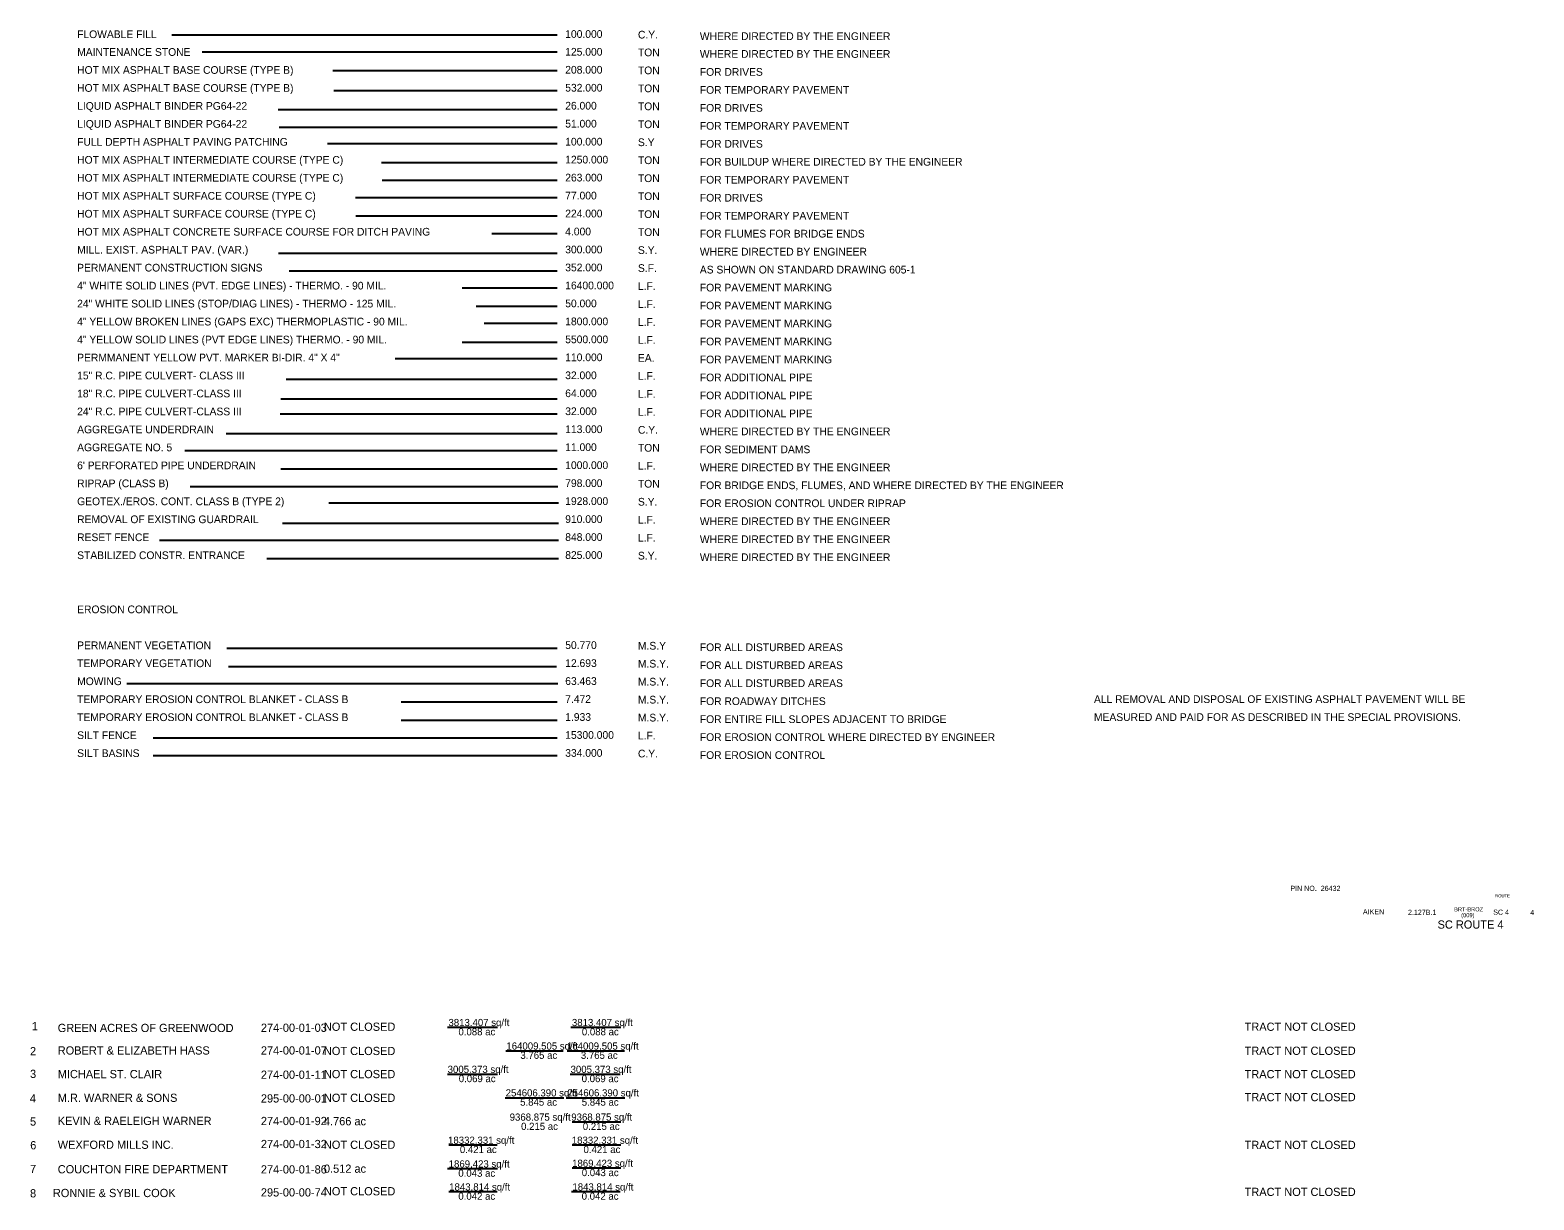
# Model space of a CAD drawing. Extents: x 17139 to 21295, y 12843 to 18076.
# Drawn here: x 17386 to 18851, y 13166 to 14305 of the extents above; entities that cross this region are included whole.
import ezdxf

# ---------------------------------------------------------------- set-up
doc = ezdxf.new("R2010")
doc.units = 0
for name, color, linetype in [('Level 1', 7, 'Continuous'), ('Level 23', 7, 'Continuous'), ('Level 3', 7, 'Continuous')]:
    doc.layers.add(name, color=color, linetype=linetype)

msp = doc.modelspace()

# ---------------------------------------------------------------- linework, layer by layer
at = {"layer": 'Level 1'}
for p, q in [((17792.8, 13334.5), (17841.4, 13334.5)), ((17912.9, 13334.5), (17961.5, 13334.5)), ((17849.5, 13311.7), (17905.3, 13311.7)), ((17909.2, 13311.7), (17965, 13311.7)), ((17792.8, 13288.9), (17841.4, 13288.9)), ((17912.2, 13288.9), (17960.8, 13288.9)), ((17848.8, 13266), (17906, 13266)), ((17908.1, 13266), (17965.3, 13266)), ((17914.2, 13242.6), (17961.3, 13242.6)), ((17793.8, 13220.2), (17840.9, 13220.2)), ((17914.2, 13220.2), (17961.3, 13220.2)), ((17792.8, 13197.1), (17841.4, 13197.1)), ((17914.2, 13197.7), (17961.3, 13197.7)), ((17793.8, 13174.5), (17841.1, 13174.5)), ((17913.5, 13174.5), (17960.7, 13174.5))]:
    msp.add_line(p, q, dxfattribs=at)
at = {"layer": 'Level 23'}
for p, q in [((17524.3, 14300.7), (17899.3, 14300.7)), ((17553.9, 14284.3), (17899.3, 14284.3)), ((17681, 14266.2), (17899.3, 14266.2)), ((17681.9, 14246.7), (17899.3, 14246.7)), ((17627.9, 14228.2), (17899.3, 14228.2)), ((17628.6, 14211), (17899.3, 14211)), ((17675.8, 14194.9), (17899.3, 14194.9)), ((17728.4, 14176.4), (17899.3, 14176.4)), ((17728.9, 14159.2), (17899.3, 14159.2)), ((17702.9, 14142.6), (17899.3, 14142.6)), ((17703.3, 14124.7), (17899.3, 14124.7)), ((17835.8, 14107.5), (17899.3, 14107.5)), ((17628, 14088.3), (17899.3, 14088.3)), ((17638.3, 14071.1), (17899.3, 14071.1)), ((17806.8, 14054.5), (17899.3, 14054.5)), ((17820.7, 14036.6), (17899.3, 14036.6)), ((17828.4, 14020.1), (17899.3, 14020.1)), ((17806.8, 14001.5), (17899.3, 14001.5)), ((17741.7, 13985.7), (17899.3, 13985.7)), ((17635.4, 13965.7), (17899.3, 13965.7)), ((17630.3, 13946.5), (17899.3, 13946.5)), ((17629.7, 13932), (17899.3, 13932)), ((17577.2, 13912.7), (17899.3, 13912.7)), ((17536.7, 13896.2), (17899.3, 13896.2)), ((17630.4, 13878.3), (17899.3, 13878.3)), ((17542, 13861.1), (17900, 13861.1)), ((17677.1, 13845.3), (17900.8, 13845.3)), ((17632.1, 13825.3), (17900.8, 13825.3)), ((17512.1, 13808.8), (17900.8, 13808.8)), ((17616.8, 13790.9), (17900.8, 13790.9)), ((17577.7, 13703.7), (17899.3, 13703.7)), ((17579.4, 13685.8), (17898.9, 13685.8)), ((17480.3, 13669.3), (17900, 13669.3)), ((17747.5, 13651.4), (17899.3, 13651.4)), ((17747.5, 13633.5), (17899.3, 13633.5)), ((17506.1, 13616.3), (17899.3, 13616.3)), ((17506.1, 13599.1), (17899.3, 13599.1))]:
    msp.add_line(p, q, dxfattribs=at)

# ---------------------------------------------------------------- texts
at = {"layer": 'Level 1'}
for s, height, p in [('3813.407 sq/ft', 7, (17793.6, 13335.7)), ('3813.407 sq/ft', 7, (17913.8, 13335.7)), ('1', 8, (17387.8, 13331.6)), ('GREEN ACRES OF GREENWOOD', 8, (17413.1, 13329.9)), ('274-00-01-03', 8, (17610.9, 13330.1)), ('NOT CLOSED', 8, (17672.3, 13331.1)), ('0.088 ac', 7, (17803.3, 13326.7)), ('0.088 ac', 7, (17923.5, 13326.7)), ('TRACT NOT CLOSED', 8, (18568.9, 13331.1)), ('2', 8, (17386.1, 13307.3)), ('ROBERT & ELIZABETH HASS', 8, (17413.1, 13308)), ('274-00-01-07', 8, (17610.9, 13308)), ('NOT CLOSED', 8, (17672.3, 13307.5)), ('164009.505 sq/ft', 7, (17850, 13312.8)), ('164009.505 sq/ft', 7, (17909, 13312.8)), ('TRACT NOT CLOSED', 8, (18568.9, 13307.7)), ('3005.373 sq/ft', 7, (17792.8, 13290.1)), ('3.765 ac', 7, (17863.6, 13303.8)), ('3005.373 sq/ft', 7, (17912.5, 13290.1)), ('3.765 ac', 7, (17922.5, 13303.8)), ('3', 8, (17386.1, 13285.2)), ('MICHAEL ST. CLAIR', 8, (17413.1, 13285)), ('274-00-01-11', 8, (17610.9, 13284.4)), ('NOT CLOSED', 8, (17672.3, 13285)), ('0.069 ac', 7, (17803.6, 13281.1)), ('0.069 ac', 7, (17923.3, 13281.1)), ('TRACT NOT CLOSED', 8, (18568.9, 13284.9)), ('4', 8, (17385.9, 13261.4)), ('M.R. WARNER & SONS', 8, (17413.1, 13261.9)), ('295-00-00-01', 8, (17610.9, 13261.3)), ('NOT CLOSED', 8, (17672.3, 13261.9)), ('254606.390 sq/ft', 7, (17849.3, 13267.2)), ('254606.390 sq/ft', 7, (17909.3, 13267.2)), ('TRACT NOT CLOSED', 8, (18568.9, 13262.6)), ('5.845 ac', 7, (17863.4, 13258.2)), ('5.845 ac', 7, (17923.4, 13258.2)), ('5', 8, (17386.1, 13238.8)), ('KEVIN & RAELEIGH WARNER', 8, (17413.1, 13239.4)), ('274-00-01-92', 8, (17610.9, 13239.3)), ('4.766 ac', 8, (17672.3, 13239.1)), ('9368.875 sq/ft', 7, (17853.2, 13243.6)), ('0.215 ac', 7, (17864.3, 13234.6)), ('9368.875 sq/ft', 7, (17913.2, 13243.6)), ('0.215 ac', 7, (17924.4, 13234.6)), ('WEXFORD MILLS INC.', 8, (17413.1, 13216.2)), ('274-00-01-32', 8, (17610.9, 13216.9)), ('NOT CLOSED', 8, (17672.3, 13216.2)), ('18332.331 sq/ft', 7, (17793.2, 13221.1)), ('18332.331 sq/ft', 7, (17913.7, 13221.1)), ('6', 8, (17386.3, 13215.7)), ('0.421 ac', 7, (17804.7, 13212.1)), ('0.421 ac', 7, (17925.1, 13212.1)), ('TRACT NOT CLOSED', 8, (18568.9, 13216)), ('7', 8, (17386.1, 13192.6)), ('COUCHTON FIRE DEPARTMENT', 8, (17413.1, 13192.3)), ('274-00-01-86', 8, (17610.9, 13192.2)), ('0.512 ac', 8, (17672.3, 13192.9)), ('1869.423 sq/ft', 7, (17793.8, 13198)), ('0.043 ac', 7, (17803.2, 13189)), ('1869.423 sq/ft', 7, (17914, 13198.6)), ('0.043 ac', 7, (17923.4, 13189.6)), ('1843.814 sq/ft', 7, (17794.3, 13175.6)), ('1843.814 sq/ft', 7, (17914.3, 13175.6)), ('8', 8, (17386.1, 13168.9)), (' RONNIE & SYBIL COOK', 8, (17405.4, 13169.2)), ('295-00-00-74', 8, (17610.9, 13169.8)), ('NOT CLOSED', 8, (17672.3, 13170.9)), ('0.042 ac', 7, (17803.2, 13166.6)), ('0.042 ac', 7, (17923.3, 13166.6)), ('TRACT NOT CLOSED', 8, (18568.9, 13170.3))]:
    msp.add_text(s, height=height, dxfattribs=at).set_placement(p)
at = {"layer": 'Level 23'}
for s, p in [('FLOWABLE FILL', (17432, 14297.7)), ('100.000', (17907.3, 14297.9)), ('C.Y.', (17978.1, 14297.3)), ('WHERE DIRECTED BY THE ENGINEER', (18038.4, 14295.8)), ('MAINTENANCE STONE', (17432, 14280.4)), ('125.000', (17907.3, 14280.6)), ('TON', (17978.1, 14280)), ('WHERE DIRECTED BY THE ENGINEER', (18038.4, 14278.5)), ('HOT MIX ASPHALT BASE COURSE (TYPE B)', (17432, 14262.9)), ('208.000', (17907.3, 14263.1)), ('TON', (17978.1, 14262.5)), ('FOR DRIVES', (18038.4, 14261)), ('HOT MIX ASPHALT BASE COURSE (TYPE B)', (17432, 14245.4)), ('532.000', (17907.3, 14245.6)), ('TON', (17978.1, 14245)), ('FOR TEMPORARY PAVEMENT', (18038.4, 14243.5)), ('LIQUID ASPHALT BINDER PG64-22', (17432, 14227.9)), ('26.000', (17907.3, 14228.1)), ('TON', (17978.1, 14227.5)), ('FOR DRIVES', (18038.4, 14226)), ('LIQUID ASPHALT BINDER PG64-22', (17432, 14210.4)), ('51.000', (17907.3, 14210.6)), ('TON', (17978.1, 14210)), ('FOR TEMPORARY PAVEMENT', (18038.4, 14208.5)), ('FULL DEPTH ASPHALT PAVING PATCHING', (17432, 14192.9)), ('100.000', (17907.3, 14193.1)), ('S.Y', (17978.1, 14192.5)), ('FOR DRIVES', (18038.4, 14191)), ('HOT MIX ASPHALT INTERMEDIATE COURSE (TYPE C)', (17432, 14175.4)), ('1250.000', (17907.3, 14175.6)), ('TON', (17978.1, 14175)), ('FOR BUILDUP WHERE DIRECTED BY THE ENGINEER', (18038.4, 14173.5)), ('HOT MIX ASPHALT INTERMEDIATE COURSE (TYPE C)', (17432, 14157.9)), ('263.000', (17907.3, 14158.1)), ('TON', (17978.1, 14157.5)), ('FOR TEMPORARY PAVEMENT', (18038.4, 14156)), ('HOT MIX ASPHALT SURFACE COURSE (TYPE C)', (17432, 14140.4)), ('77.000', (17907.3, 14140.6)), ('TON', (17978.1, 14140)), ('FOR DRIVES', (18038.4, 14138.5)), ('HOT MIX ASPHALT SURFACE COURSE (TYPE C)', (17432, 14122.9)), ('224.000', (17907.3, 14123.1)), ('TON', (17978.1, 14122.5)), ('FOR TEMPORARY PAVEMENT', (18038.4, 14121)), ('HOT MIX ASPHALT CONCRETE SURFACE COURSE FOR DITCH PAVING', (17432, 14105.4)), ('4.000', (17907.3, 14105.6)), ('TON', (17978.1, 14105)), ('FOR FLUMES FOR BRIDGE ENDS', (18038.4, 14103.5)), ('MILL. EXIST. ASPHALT PAV. (VAR.)', (17432, 14087.9)), ('300.000', (17907.3, 14088.1)), ('S.Y.', (17978.1, 14087.5)), ('WHERE DIRECTED BY ENGINEER', (18038.4, 14086)), ('PERMANENT CONSTRUCTION SIGNS', (17432, 14070.4)), ('352.000', (17907.3, 14070.6)), ('S.F.', (17978.1, 14070)), ('AS SHOWN ON STANDARD DRAWING 605-1', (18038.4, 14068.5)), ('4" WHITE SOLID LINES (PVT. EDGE LINES) - THERMO. - 90 MIL.', (17432, 14052.9)), ('16400.000', (17907.3, 14053.1)), ('L.F.', (17978.1, 14052.5)), ('FOR PAVEMENT MARKING', (18038.4, 14051)), ('24" WHITE SOLID LINES (STOP/DIAG LINES) - THERMO - 125 MIL.', (17432, 14035.4)), ('50.000', (17907.3, 14035.6)), ('L.F.', (17978.1, 14035)), ('FOR PAVEMENT MARKING', (18038.4, 14033.5)), ('4" YELLOW BROKEN LINES (GAPS EXC) THERMOPLASTIC - 90 MIL.', (17432, 14017.9)), ('1800.000', (17907.3, 14018.1)), ('L.F.', (17978.1, 14017.5)), ('FOR PAVEMENT MARKING', (18038.4, 14016)), ('4" YELLOW SOLID LINES (PVT EDGE LINES) THERMO. - 90 MIL.', (17432, 14000.4)), ('5500.000', (17907.3, 14000.6)), ('L.F.', (17978.1, 14000)), ('FOR PAVEMENT MARKING', (18038.4, 13998.5)), ('PERMMANENT YELLOW PVT. MARKER BI-DIR. 4" X 4"', (17432, 13982.9)), ('110.000', (17907.3, 13983.1)), ('EA.', (17978.1, 13982.5)), ('FOR PAVEMENT MARKING', (18038.4, 13981)), ('15" R.C. PIPE CULVERT- CLASS III', (17432, 13965.4)), ('32.000', (17907.3, 13965.6)), ('L.F.', (17978.1, 13965)), ('FOR ADDITIONAL PIPE', (18038.4, 13963.5)), ('18" R.C. PIPE CULVERT-CLASS III', (17432, 13947.9)), ('64.000', (17907.3, 13948.1)), ('L.F.', (17978.1, 13947.5)), ('FOR ADDITIONAL PIPE', (18038.4, 13946)), ('24" R.C. PIPE CULVERT-CLASS III', (17432, 13930.4)), ('32.000', (17907.3, 13930.6)), ('L.F.', (17978.1, 13930)), ('FOR ADDITIONAL PIPE', (18038.4, 13928.5)), ('AGGREGATE UNDERDRAIN', (17432, 13912.9)), ('113.000', (17907.3, 13913.1)), ('C.Y.', (17978.1, 13912.5)), ('WHERE DIRECTED BY THE ENGINEER', (18038.4, 13911)), ('AGGREGATE NO. 5', (17432, 13895.4)), ('11.000', (17907.3, 13895.6)), ('TON', (17978.1, 13895)), ('FOR SEDIMENT DAMS', (18038.4, 13893.5)), ("6' PERFORATED PIPE UNDERDRAIN", (17432, 13877.9)), ('1000.000', (17907.3, 13878.1)), ('L.F.', (17978.1, 13877.5)), ('WHERE DIRECTED BY THE ENGINEER', (18038.4, 13876)), ('RIPRAP (CLASS B)', (17432, 13860.4)), ('798.000', (17907.3, 13860.6)), ('TON', (17978.1, 13860)), ('FOR BRIDGE ENDS, FLUMES, AND WHERE DIRECTED BY THE ENGINEER', (18038.4, 13858.5)), ('GEOTEX./EROS. CONT. CLASS B (TYPE 2)', (17432, 13842.9)), ('1928.000', (17907.3, 13843.1)), ('S.Y.', (17978.1, 13842.5)), ('FOR EROSION CONTROL UNDER RIPRAP', (18038.4, 13841)), ('REMOVAL OF EXISTING GUARDRAIL', (17432, 13825.4)), ('910.000', (17907.3, 13825.6)), ('L.F.', (17978.1, 13825)), ('WHERE DIRECTED BY THE ENGINEER', (18038.4, 13823.5)), ('RESET FENCE', (17432, 13807.9)), ('848.000', (17907.3, 13808.1)), ('L.F.', (17978.1, 13807.5)), ('WHERE DIRECTED BY THE ENGINEER', (18038.4, 13806)), ('STABILIZED CONSTR. ENTRANCE', (17432, 13790.4)), ('825.000', (17907.3, 13790.6)), ('S.Y.', (17978.1, 13790)), ('WHERE DIRECTED BY THE ENGINEER', (18038.4, 13788.5)), ('EROSION CONTROL', (17432, 13737.7)), ('PERMANENT VEGETATION', (17432, 13702.7)), ('50.770', (17907.3, 13702.9)), ('M.S.Y', (17978.1, 13702.3)), ('FOR ALL DISTURBED AREAS', (18038.4, 13700.8)), ('TEMPORARY VEGETATION', (17432, 13685.2)), ('12.693', (17907.3, 13685.4)), ('M.S.Y.', (17978.1, 13684.8)), ('FOR ALL DISTURBED AREAS', (18038.4, 13683.3)), ('MOWING', (17432, 13667.7)), ('63.463', (17907.3, 13667.9)), ('M.S.Y.', (17978.1, 13667.3)), ('FOR ALL DISTURBED AREAS', (18038.4, 13665.8)), ('TEMPORARY EROSION CONTROL BLANKET - CLASS B', (17432, 13650.2)), ('7.472', (17907.3, 13650.4)), ('M.S.Y.', (17978.1, 13649.8)), ('FOR ROADWAY DITCHES', (18038.4, 13648.3)), ('ALL REMOVAL AND DISPOSAL OF EXISTING ASPHALT PAVEMENT WILL BE', (18422.2, 13650.3)), ('TEMPORARY EROSION CONTROL BLANKET - CLASS B', (17432, 13632.7)), ('1.933', (17907.3, 13632.9)), ('M.S.Y.', (17978.1, 13632.3)), ('FOR ENTIRE FILL SLOPES ADJACENT TO BRIDGE', (18038.4, 13630.8)), ('MEASURED AND PAID FOR AS DESCRIBED IN THE SPECIAL PROVISIONS.', (18422.2, 13632.8)), ('SILT FENCE', (17432, 13615.2)), ('15300.000', (17907.3, 13615.4)), ('L.F.', (17978.1, 13614.8)), ('FOR EROSION CONTROL WHERE DIRECTED BY ENGINEER', (18038.4, 13613.3)), ('SILT BASINS', (17432, 13597.7)), ('334.000', (17907.3, 13597.9)), ('C.Y.', (17978.1, 13597.3)), ('FOR EROSION CONTROL', (18038.4, 13595.8))]:
    msp.add_text(s, height=7.5, dxfattribs=at).set_placement(p)
at = {"layer": 'Level 3'}
for s, height, p in [('PIN NO.  26432', 5, (18613.5, 13467.3)), ('ROUTE', 3, (18812.8, 13461)), ('AIKEN', 5, (18684.1, 13444.5)), (' 2.127B.1', 5, (18726.1, 13444)), ('BRT-BROZ', 4, (18772.9, 13447.4)), ('(009)', 4, (18779.8, 13441.7)), ('SC 4', 5, (18811, 13444.1)), ('4', 5, (18847.1, 13443.8)), ('SC ROUTE 4', 8, (18756.8, 13430.6))]:
    msp.add_text(s, height=height, dxfattribs=at).set_placement(p)

doc.saveas('drawing.dxf')
